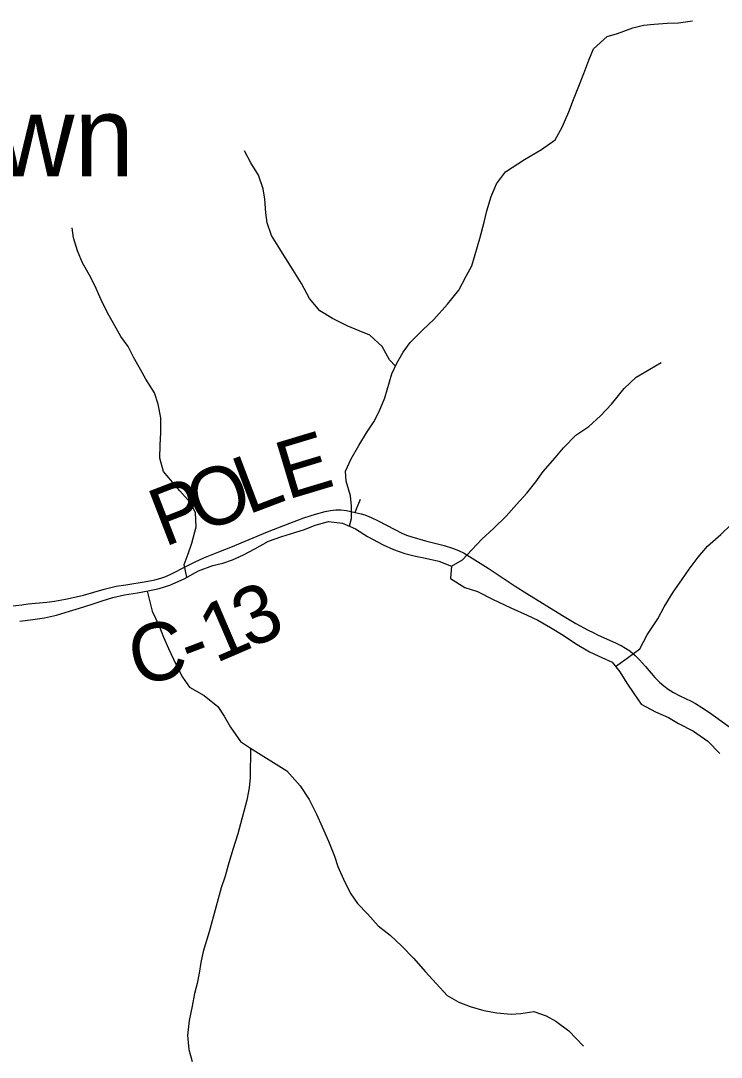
# Model space of a CAD drawing. Extents: x 0 to 34, y 0 to 22.
# Drawn here: x 6.579 to 7.268, y 17.482 to 18.501 of the extents above; entities that cross this region are included whole.
import ezdxf

# ---------------------------------------------------------------- set-up
doc = ezdxf.new("R2010")
doc.units = 0
for name, color, linetype in [('GM_X_County_Road', 7, 'Continuous'), ('GM_X_County_Road_Text', 7, 'Continuous'), ('GM_X_Minor_River', 7, 'Continuous'), ('GM_X_Township_Road', 7, 'Continuous'), ('GM_X_Unincorporated_Text', 7, 'Continuous')]:
    doc.layers.add(name, color=color, linetype=linetype)

msp = doc.modelspace()

# ---------------------------------------------------------------- linework, layer by layer
at = {"layer": 'GM_X_County_Road'}
for points in [[(6.5715, 17.926), (6.5802, 17.9271), (6.5863, 17.9278), (6.6049, 17.9296), (6.6122, 17.9306), (6.6232, 17.9325), (6.6336, 17.9347), (6.6408, 17.9366), (6.6611, 17.9423), (6.6732, 17.9452), (6.6824, 17.9467), (6.7026, 17.9499), (6.7112, 17.9516), (6.7171, 17.9532), (6.7218, 17.9549), (6.728, 17.9578), (6.7408, 17.9642), (6.7502, 17.969), (6.7592, 17.9732), (6.7742, 17.979), (6.7858, 17.9835), (6.8219, 17.9987), (6.8438, 18.0073), (6.8578, 18.0124), (6.8691, 18.016), (6.8787, 18.0186), (6.8841, 18.0198), (6.8891, 18.0203), (6.894, 18.0203), (6.8996, 18.0196), (6.9083, 18.0179)], [(6.9083, 18.0179), (6.9141, 18.0165), (6.9177, 18.0153), (6.924, 18.0127), (6.9308, 18.0096), (6.9472, 18.0009), (6.9542, 17.9973), (6.9586, 17.9955), (6.964, 17.9937), (6.9773, 17.9899), (6.9958, 17.9854), (7.0041, 17.9828), (7.0099, 17.9804), (7.0155, 17.9776), (7.0235, 17.9728), (7.0392, 17.963), (7.0658, 17.9454), (7.0772, 17.938), (7.1121, 17.9166), (7.1254, 17.9087), (7.1374, 17.9021), (7.1423, 17.8996), (7.1473, 17.8972), (7.1644, 17.8897), (7.1691, 17.8874)], [(7.1691, 17.8874), (7.17, 17.887), (7.1743, 17.8844), (7.1784, 17.8816), (7.1836, 17.8771), (7.188, 17.8728), (7.1938, 17.8663), (7.2031, 17.8556), (7.2078, 17.8508), (7.2119, 17.8472), (7.2163, 17.8439), (7.2215, 17.8407), (7.2276, 17.8376), (7.2388, 17.8322), (7.2431, 17.8298), (7.2495, 17.8259), (7.2568, 17.821), (7.2804, 17.8039)]]:
    msp.add_lwpolyline(points, dxfattribs=at)
at = {"layer": 'GM_X_Minor_River'}
for points in [[(6.9026, 18.0044), (6.9047, 18.0118), (6.9045, 18.0239), (6.9035, 18.0341), (6.8995, 18.0486), (6.8988, 18.0585), (6.9043, 18.0705), (6.9117, 18.0837), (6.9194, 18.0961), (6.9267, 18.107), (6.9318, 18.1172), (6.9373, 18.1304), (6.9444, 18.1542), (6.9491, 18.1647), (6.9553, 18.1753), (6.9622, 18.185), (6.9749, 18.1974), (6.9856, 18.2075), (6.9991, 18.2225), (7.0103, 18.2363), (7.0173, 18.2503), (7.0231, 18.2604), (7.0263, 18.2714), (7.031, 18.2873), (7.035, 18.3031), (7.0378, 18.3145), (7.0421, 18.3284), (7.0472, 18.3409), (7.0561, 18.3529), (7.0748, 18.3648), (7.0916, 18.3748), (7.105, 18.3841), (7.112, 18.3965), (7.1186, 18.4116), (7.123, 18.424), (7.1284, 18.4369), (7.1331, 18.4493), (7.1382, 18.4625), (7.1429, 18.4738), (7.1563, 18.4858), (7.1662, 18.4887), (7.1815, 18.4945), (7.1921, 18.4971), (7.2024, 18.4981), (7.2153, 18.499), (7.2263, 18.4992), (7.2403, 18.5013)], [(6.9478, 18.1618), (6.9419, 18.1679), (6.9349, 18.1809), (6.9225, 18.192), (6.9123, 18.1963), (6.9003, 18.2014), (6.8859, 18.2085), (6.8735, 18.2162), (6.8634, 18.2281), (6.8553, 18.243), (6.8471, 18.256), (6.8401, 18.2675), (6.8326, 18.2797), (6.8259, 18.2901), (6.8215, 18.3026), (6.8202, 18.3125), (6.8192, 18.3258), (6.8178, 18.3361), (6.813, 18.3494), (6.8056, 18.3616), (6.7993, 18.3735)], [(6.7427, 17.9542), (6.74, 17.9666), (6.7439, 17.9772), (6.7474, 17.9877), (6.7518, 18.0036), (6.7512, 18.0173), (6.7464, 18.0268), (6.7356, 18.0391), (6.7195, 18.0579), (6.7159, 18.0712), (6.7164, 18.0841), (6.717, 18.0963), (6.7171, 18.1107), (6.7143, 18.1244), (6.7106, 18.1354), (6.7021, 18.1488), (6.6969, 18.1583), (6.6902, 18.1706), (6.6847, 18.1809), (6.6776, 18.1908), (6.6642, 18.2149), (6.6583, 18.2268), (6.6521, 18.2409), (6.6469, 18.2512), (6.6398, 18.2634), (6.6351, 18.2752), (6.631, 18.2878), (6.6296, 18.2977)], [(7.0031, 17.9649), (7.0138, 17.9712), (7.023, 17.9809), (7.033, 17.9914), (7.0445, 18.0019), (7.0568, 18.0142), (7.0671, 18.0255), (7.0771, 18.0367), (7.086, 18.0479), (7.0933, 18.0581), (7.1049, 18.0716), (7.1133, 18.0813), (7.1252, 18.0937), (7.1382, 18.1022), (7.1497, 18.1127), (7.1605, 18.1243), (7.1728, 18.1397), (7.1847, 18.1509), (7.1981, 18.1587), (7.2092, 18.1653)], [(6.5781, 17.9108), (6.5911, 17.9125), (6.6025, 17.9143), (6.6142, 17.9168), (6.6272, 17.9207), (6.6371, 17.9236), (6.6485, 17.9273), (6.6592, 17.9309), (6.6698, 17.9342), (6.6812, 17.9367), (6.6941, 17.9388), (6.7044, 17.9406), (6.7154, 17.9431), (6.7257, 17.9463), (6.7398, 17.9526), (6.7539, 17.9604), (6.768, 17.9655), (6.7779, 17.968), (6.7874, 17.9713), (6.7985, 17.976), (6.8095, 17.982), (6.8229, 17.9897), (6.8359, 17.9941), (6.8488, 17.9981), (6.8583, 18.001), (6.869, 18.0054), (6.8819, 18.009), (6.8959, 18.0073), (6.9084, 18.0018), (6.9204, 17.9941), (6.9358, 17.9859), (6.946, 17.9812), (6.957, 17.9773), (6.9675, 17.9749), (6.9774, 17.9728), (6.9906, 17.97), (7.0031, 17.9649), (7.0021, 17.9528), (7.0161, 17.9439), (7.0285, 17.9399), (7.0432, 17.9325), (7.0613, 17.9239), (7.0775, 17.9168), (7.0881, 17.9118), (7.1005, 17.9048), (7.1129, 17.897), (7.1249, 17.8889), (7.1389, 17.8807), (7.1509, 17.8753), (7.1611, 17.8706), (7.1686, 17.861), (7.1756, 17.8499), (7.1823, 17.8399), (7.1898, 17.8292), (7.2037, 17.8218), (7.2165, 17.816), (7.2263, 17.8101), (7.241, 17.8027)], [(7.1644, 17.8664), (7.1759, 17.8745), (7.1882, 17.8838), (7.1956, 17.8974), (7.206, 17.9132), (7.2122, 17.9249), (7.2211, 17.9395), (7.2296, 17.9515), (7.2369, 17.9621), (7.2458, 17.9737), (7.255, 17.9846), (7.2681, 17.9962), (7.2781, 18.0059)], [(6.7034, 17.9404), (6.7083, 17.9208), (6.715, 17.907), (6.7197, 17.8952), (6.7245, 17.8841), (6.7319, 17.8685), (6.7382, 17.8559), (6.7453, 17.8459), (6.7596, 17.8378), (6.7731, 17.827), (6.7794, 17.8174), (6.7857, 17.8067), (6.7954, 17.7925), (6.8052, 17.7859)], [(7.241, 17.8027), (7.2553, 17.793), (7.2669, 17.7808)], [(6.8052, 17.7859), (6.8049, 17.757), (6.804, 17.7471), (6.8015, 17.735), (6.7927, 17.7017), (6.7879, 17.6862), (6.7831, 17.6711), (6.7803, 17.6601), (6.7764, 17.6488), (6.7675, 17.6162), (6.7647, 17.6053), (6.7588, 17.586), (6.7563, 17.5754), (6.7547, 17.5648), (6.7526, 17.5545), (6.7502, 17.5447), (6.7477, 17.5322), (6.7449, 17.5182), (6.7432, 17.5034), (6.7445, 17.4897), (6.7477, 17.4779)], [(6.8052, 17.7859), (6.841, 17.7637), (6.854, 17.7491), (6.8629, 17.7356), (6.8703, 17.7211), (6.8758, 17.7085), (6.8821, 17.6947), (6.8879, 17.6798), (6.8912, 17.6695), (6.8982, 17.6542), (6.904, 17.6427), (6.9104, 17.6331), (6.9204, 17.6231), (6.9309, 17.6112), (6.9425, 17.6022), (6.9541, 17.5914), (6.9657, 17.5795), (6.9773, 17.566), (6.9989, 17.5429), (7.0102, 17.5363), (7.0215, 17.5319), (7.0347, 17.5279), (7.0476, 17.5258), (7.0616, 17.5245), (7.0711, 17.5251), (7.084, 17.5272), (7.0961, 17.5228), (7.1058, 17.5177), (7.1186, 17.5081), (7.1328, 17.493)]]:
    msp.add_lwpolyline(points, dxfattribs=at)
at = {"layer": 'GM_X_Township_Road'}
msp.add_lwpolyline([(6.9083, 18.0179), (6.9096, 18.0214), (6.9111, 18.0254), (6.9135, 18.0309)], dxfattribs=at)

# ---------------------------------------------------------------- texts
at = {"layer": 'GM_X_County_Road_Text'}
for s, rotation, p in [('E', 16.7573, (6.8413, 18.0301)), ('L', 20.7873, (6.8025, 18.0153)), ('O', 21.1517, (6.756, 17.9973)), ('P', 21.1544, (6.7202, 17.9835)), ('3', 23.7246, (6.8033, 17.8832)), ('1', 23.3126, (6.7708, 17.8692)), ('C', 12.8955, (6.6927, 17.847)), ('-', 20.6964, (6.7463, 17.8599))]:
    msp.add_text(s, height=0.0568, rotation=rotation, dxfattribs=at).set_placement(p)
at = {"layer": 'GM_X_Unincorporated_Text'}
msp.add_text('Stringtown', height=0.07898, rotation=0, dxfattribs=at).set_placement((6.1917, 18.3484))

doc.saveas('drawing.dxf')
